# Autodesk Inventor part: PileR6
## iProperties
Created: 2010-07
Part Number: PileR6
Document SubType Name: Modeling
Designer: eric
Density: 1 g/cm^3
Mass: 6.38677 g
Surface Area: 22.3588 cm^2
Volume: 6.38677 cm^3
Author: eric
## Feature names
1. Revolution1
2. Fillet3
3. Fillet2
4. Fillet1
